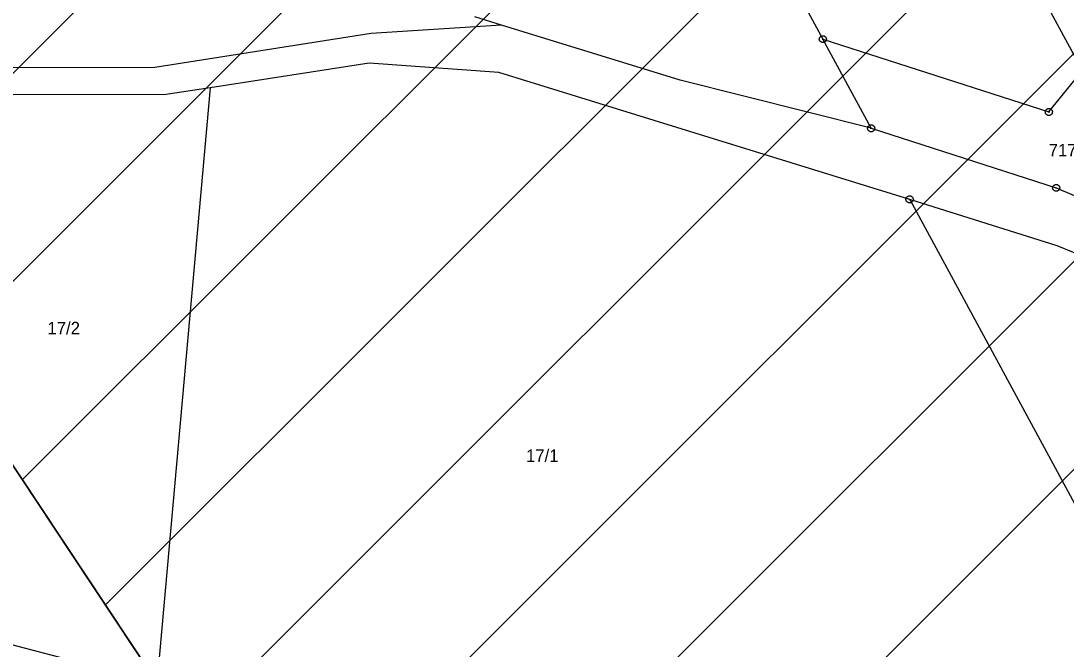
# Model space of a CAD drawing. Extents: x -593358 to -590116, y -1072518 to -1068420.
# Drawn here: x -591520.7 to -591378.7, y -1070372.5 to -1070287.1 of the extents above; entities that cross this region are included whole.
import ezdxf

# ---------------------------------------------------------------- set-up
doc = ezdxf.new("R2010")
doc.units = 0
for name, color, linetype in [('Parcela KN', 7, 'Continuous'), ('Parcelní číslo', 7, 'Continuous'), ('Vrstva 24', 7, 'Continuous'), ('zastavitelné území', 7, 'Continuous')]:
    doc.layers.add(name, color=color, linetype=linetype)

msp = doc.modelspace()

# ---------------------------------------------------------------- linework, layer by layer
at = {"layer": 'Parcela KN'}
for p, q in [((-591376.47, -1070293.83), (-591393.59, -1070262.18)), ((-591420.4, -1070273.59), (-591411.76, -1070289.56)), ((-591455.44, -1070287.63), (-591459.06, -1070286.51)), ((-591455.44, -1070287.63), (-591473.14, -1070288.79)), ((-591431.13, -1070295.14), (-591455.44, -1070287.63)), ((-591473.14, -1070288.79), (-591502.51, -1070293.42)), ((-591411.76, -1070289.56), (-591381.06, -1070299.45)), ((-591405.2, -1070301.67), (-591411.76, -1070289.56)), ((-591473.42, -1070292.82), (-591495.02, -1070296.16)), ((-591455.77, -1070294.07), (-591473.42, -1070292.82)), ((-591502.51, -1070293.42), (-591550.87, -1070293.51)), ((-591399.97, -1070311.34), (-591455.77, -1070294.07)), ((-591381.06, -1070299.45), (-591376.47, -1070293.83)), ((-591405.2, -1070301.67), (-591431.13, -1070295.14)), ((-591501.3, -1070297.13), (-591530.86, -1070297.05)), ((-591495.02, -1070296.16), (-591502.24, -1070376.99)), ((-591495.02, -1070296.16), (-591501.3, -1070297.13)), ((-591405.2, -1070301.67), (-591380.05, -1070309.77)), ((-591380.05, -1070309.77), (-591374.82, -1070312.01)), ((-591399.97, -1070311.34), (-591367.46, -1070371.43)), ((-591379.95, -1070317.65), (-591399.97, -1070311.34)), ((-591339.96, -1070334.1), (-591379.95, -1070317.65)), ((-591525.44, -1070342.06), (-591502.24, -1070376.99)), ((-591525.57, -1070370.91), (-591502.24, -1070376.99))]:
    msp.add_line(p, q, dxfattribs=at)
at = {"layer": 'Vrstva 24'}
for p, q in [((-591411.88, -1070289.56), (-591411.64, -1070289.56)), ((-591381.18, -1070299.45), (-591380.94, -1070299.45)), ((-591405.32, -1070301.67), (-591405.08, -1070301.67)), ((-591380.17, -1070309.77), (-591379.93, -1070309.77)), ((-591400.09, -1070311.34), (-591399.85, -1070311.34))]:
    msp.add_line(p, q, dxfattribs=at)
for points in [[(-591411.61, -1070289.08), (-591411.36, -1070289.26), (-591411.26, -1070289.55), (-591411.36, -1070289.84), (-591411.61, -1070290.02), (-591411.92, -1070290.02), (-591412.17, -1070289.84), (-591412.27, -1070289.55), (-591412.17, -1070289.26), (-591411.92, -1070289.08)], [(-591380.91, -1070298.97), (-591380.66, -1070299.15), (-591380.56, -1070299.44), (-591380.66, -1070299.73), (-591380.91, -1070299.91), (-591381.22, -1070299.91), (-591381.47, -1070299.73), (-591381.57, -1070299.44), (-591381.47, -1070299.15), (-591381.22, -1070298.97)], [(-591405.05, -1070301.19), (-591404.8, -1070301.37), (-591404.7, -1070301.66), (-591404.8, -1070301.95), (-591405.05, -1070302.13), (-591405.36, -1070302.13), (-591405.61, -1070301.95), (-591405.71, -1070301.66), (-591405.61, -1070301.37), (-591405.36, -1070301.19)], [(-591379.9, -1070309.29), (-591379.65, -1070309.47), (-591379.55, -1070309.76), (-591379.65, -1070310.05), (-591379.9, -1070310.23), (-591380.21, -1070310.23), (-591380.46, -1070310.05), (-591380.56, -1070309.76), (-591380.46, -1070309.47), (-591380.21, -1070309.29)], [(-591399.82, -1070310.86), (-591399.57, -1070311.04), (-591399.47, -1070311.33), (-591399.57, -1070311.62), (-591399.82, -1070311.8), (-591400.13, -1070311.8), (-591400.38, -1070311.62), (-591400.48, -1070311.33), (-591400.38, -1070311.04), (-591400.13, -1070310.86)]]:
    msp.add_lwpolyline(points, close=True, dxfattribs=at)
at = {"layer": 'zastavitelné území'}
for p, q in [((-591530.725, -1070303.099), (-591218.628, -1069991.002)), ((-591530.106, -1070330.765), (-591209.771, -1070010.429)), ((-591520.522, -1070349.464), (-591200.819, -1070029.761)), ((-591509.234, -1070366.46), (-591191.409, -1070048.635)), ((-591511.223, -1070396.734), (-591184.75, -1070070.261)), ((-591535.698, -1070449.493), (-591179.315, -1070093.111)), ((-591513.288, -1070455.368), (-591170.017, -1070112.097)), ((-591467.818, -1070438.181), (-591160.472, -1070130.836))]:
    msp.add_line(p, q, dxfattribs=at)
msp.add_lwpolyline([(-591502.24, -1070376.99), (-591513.84, -1070359.525), (-591525.44, -1070342.06), (-591527.725, -1070338.57), (-591530.01, -1070335.08), (-591530.435, -1070316.065), (-591530.86, -1070297.05)], dxfattribs=at)

# ---------------------------------------------------------------- texts
at = {"layer": 'Parcelní číslo'}
for s, p in [('717/94', (-591381.084, -1070305.49)), ('17/2', (-591517.109, -1070329.68)), ('17/1', (-591452.098, -1070347.02))]:
    msp.add_text(s, height=1.7, dxfattribs=at).set_placement(p)

doc.saveas('drawing.dxf')
